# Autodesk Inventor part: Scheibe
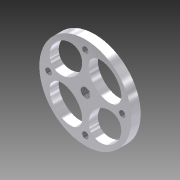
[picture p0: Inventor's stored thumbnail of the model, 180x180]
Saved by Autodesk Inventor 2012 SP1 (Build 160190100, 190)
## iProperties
Created: 2012-10
Part Number: Scheibe
Material: Default
Document SubType Name: Modeling
Designer: Dominic Mähling
Density: 1 g/cm^3
Author: Dominic Mähling
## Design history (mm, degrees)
derived "Funkenstrecke master.ipt"
feature "Scheibe::Funkenstrecke master.ipt" dims "d0" = 10
tag "Bezeichnung1"
node "Volumenkörper1"
other parameters: "sa_0" = 0, "sa_1" = 0, "sa_2" = 3e+07, "sa_3" = 3e+07, "sa_4" = 0, "sa_5" = 0, "sa_6" = -3e+07, "sa_7" = 0, "sa_8" = 0, "sa_9" = 0, "sa_10" = 0, "sa_11" = -3e+07
